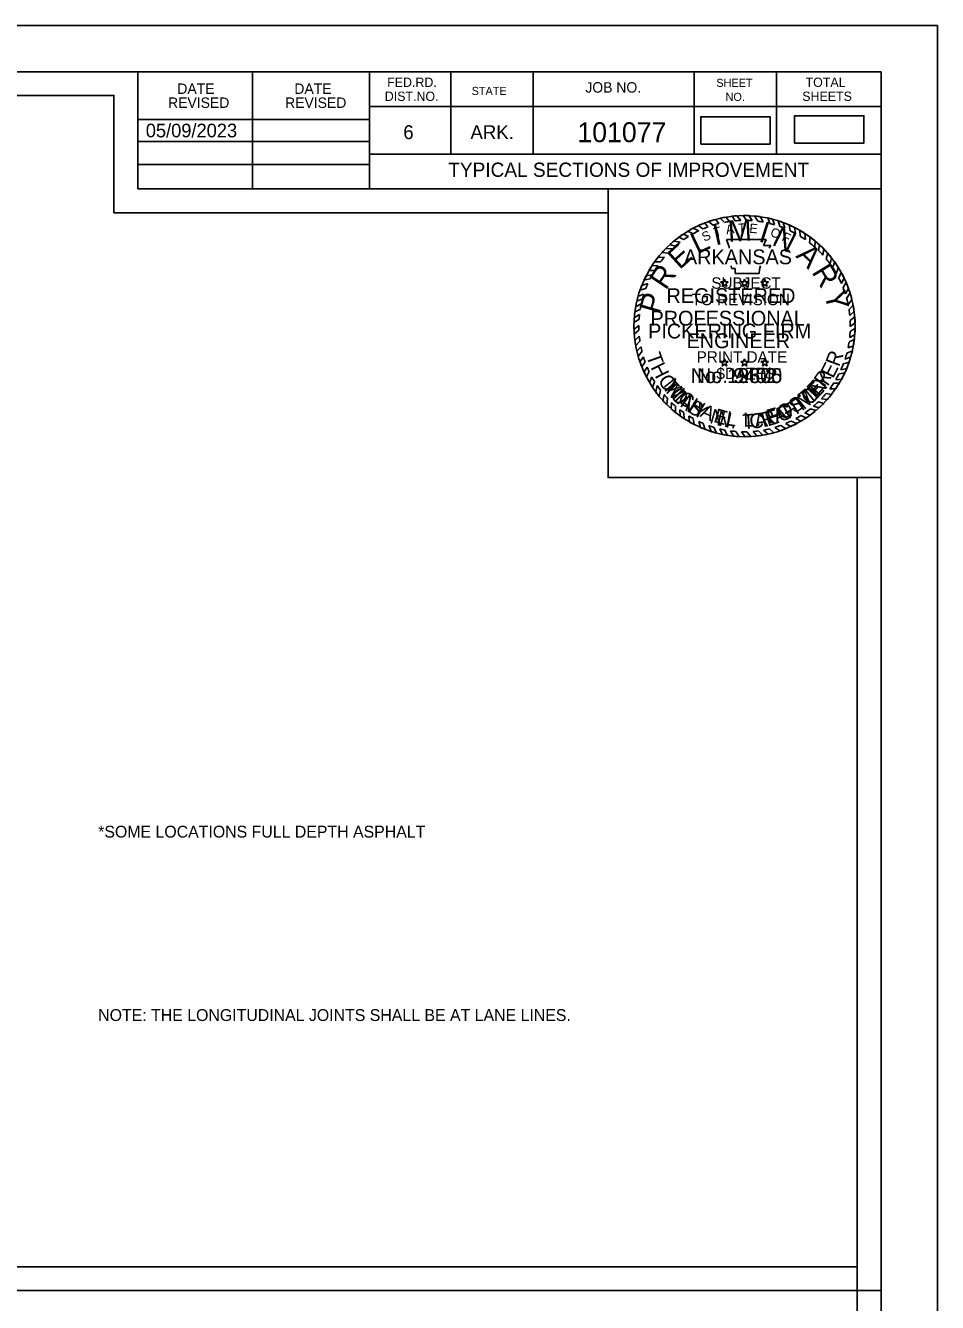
# Model space of a CAD drawing. Extents: x 1368357 to 1371690, y 378199 to 380332.
# Drawn here: x 1370922 to 1371690, y 379256 to 380332 of the extents above; entities that cross this region are included whole.
import ezdxf

# ---------------------------------------------------------------- set-up
doc = ezdxf.new("R2010")
doc.units = 0
for name, color, linetype in [('Default', 7, 'Continuous'), ('R_Border', 7, 'Continuous'), ('R_Border Notes', 7, 'Continuous'), ('R_Border Plan-Plan', 7, 'Continuous'), ('R_No Plot', 7, 'Continuous'), ('R_Revision Date Text', 7, 'Continuous'), ('STAMP_PE_CRAFTON', 7, 'Continuous'), ('STAMP_PE_FOSTER', 7, 'Continuous'), ('STAMP_PE_SEAL-INFO', 7, 'Continuous'), ('STAMP_PE_TAEGTMEYER', 7, 'Continuous'), ('STAMP_PE_TXT', 7, 'Continuous'), ('STAMP_PRELIMINARY', 7, 'Continuous'), ('Text', 7, 'Continuous')]:
    doc.layers.add(name, color=color, linetype=linetype)

msp = doc.modelspace()

# ---------------------------------------------------------------- linework, layer by layer
at = {"layer": 'Default'}
for points in [[(1371490.9, 380232.5), (1371549.3, 380232.5), (1371549.3, 380255.6), (1371490.9, 380255.6)], [(1371570, 380233.3), (1371628.3, 380233.3), (1371628.3, 380256.4), (1371570, 380256.4)]]:
    msp.add_lwpolyline(points, close=True, dxfattribs=at)
at = {"layer": 'R_Border'}
for p, q in [((1368481, 380293.5), (1371642.8, 380293.5)), ((1371016.4, 380194.7), (1371016.4, 380293.5)), ((1371113.2, 380194.7), (1371113.2, 380293.5)), ((1371211.8, 380293.5), (1371211.8, 380194.7)), ((1371280.2, 380293.5), (1371280.2, 380224.1)), ((1371349.6, 380293.5), (1371349.6, 380224.1)), ((1371485.4, 380293.5), (1371485.4, 380224.1)), ((1371554.8, 380293.5), (1371554.8, 380224.1)), ((1371642.8, 378238.9), (1371642.8, 380293.5)), ((1371642.8, 380264.1), (1371211.8, 380264.1)), ((1371642.8, 380264.3), (1371642.8, 380264.3)), ((1371016.4, 380253.3), (1371211.8, 380253.3)), ((1371016.4, 380234.7), (1371211.8, 380234.7)), ((1371642.8, 380224.1), (1371211.8, 380224.1)), ((1371241.4, 380224.1), (1371642.8, 380224.1)), ((1371016.4, 380215.3), (1371211.8, 380215.3)), ((1371642.8, 380194.7), (1371016.4, 380194.7))]:
    msp.add_line(p, q, dxfattribs=at)
at = {"layer": 'R_Border Plan-Plan'}
msp.add_line((1368481, 379266.2), (1371642.8, 379266.2), dxfattribs=at)
at = {"layer": 'R_No Plot'}
for points in [[(1368356.9, 380332.4), (1371690.3, 380332.4), (1371690.3, 378199), (1368356.9, 378199)], [(1371622.8, 379286.2), (1368501, 379286.2), (1368501, 380273.5), (1370996.4, 380273.5), (1370996.4, 380174.7), (1371171.8, 380174.7), (1371412.8, 380174.7), (1371412.8, 379951.4), (1371622.8, 379951.4)], [(1368501, 380273.5), (1370996.4, 380273.5), (1370996.4, 380174.7), (1371171.8, 380174.7), (1371412.8, 380174.7), (1371412.8, 379951.4), (1371622.8, 379951.4), (1371622.8, 378258.9), (1368501, 378258.9)], [(1371412.8, 380194.7), (1371642.8, 380194.7), (1371642.8, 379951.4), (1371412.8, 379951.4)]]:
    msp.add_lwpolyline(points, close=True, dxfattribs=at)
at = {"layer": 'STAMP_PE_SEAL-INFO'}
for p, q in [((1371488.8, 380163.8), (1371492.7, 380161.1)), ((1371493.9, 380166), (1371496.9, 380162.7)), ((1371497.4, 380167.2), (1371501.2, 380164.2)), ((1371503.3, 380169.1), (1371506.2, 380165.6)), ((1371507.2, 380170), (1371510.7, 380166.6)), ((1371512, 380171), (1371515, 380167.3)), ((1371517.2, 380171.7), (1371520, 380167.9)), ((1371524.5, 380168.2), (1371521.4, 380172.1)), ((1371529.5, 380168.2), (1371526.7, 380172.3)), ((1371534.1, 380168), (1371531.5, 380172.3)), ((1371539.1, 380167.5), (1371536.2, 380171.9)), ((1371543.4, 380166.9), (1371540.8, 380171.4)), ((1371549, 380165.7), (1371547.3, 380170.3)), ((1371553, 380164.6), (1371551.4, 380169.3)), ((1371557.5, 380163.1), (1371556.1, 380167.9)), ((1371561.7, 380161.5), (1371560.3, 380166.5)), ((1371566.3, 380159.5), (1371565.3, 380164.4)), ((1371472, 380154.1), (1371476.5, 380152)), ((1371476.2, 380156.7), (1371480.6, 380154.7)), ((1371480.1, 380159.2), (1371484.4, 380156.9)), ((1371484.5, 380161.7), (1371489.2, 380159.4)), ((1371512.5, 380152), (1371546, 380152)), ((1371513.7, 380148.9), (1371512.5, 380152)), ((1371546, 380152), (1371543.7, 380147.1)), ((1371570.8, 380157.2), (1371569.9, 380162.3)), ((1371574.7, 380154.9), (1371574.3, 380159.9)), ((1371579, 380152.1), (1371578.7, 380157.2)), ((1371582.6, 380149.4), (1371583, 380154.3)), ((1371458.2, 380141.1), (1371463.4, 380140.7)), ((1371461.4, 380144.6), (1371466.9, 380144.2)), ((1371464.8, 380147.8), (1371469.4, 380146.4)), ((1371468.2, 380150.8), (1371473.5, 380149.8)), ((1371514.8, 380146), (1371513.7, 380148.9)), ((1371514.9, 380144.8), (1371514.8, 380146)), ((1371543.7, 380147.1), (1371550, 380147.1)), ((1371550, 380147.1), (1371548.6, 380144.8)), ((1371587.1, 380145.7), (1371587.3, 380150.9)), ((1371590.2, 380142.7), (1371590.9, 380147.7)), ((1371593.8, 380139), (1371594.5, 380144.3)), ((1371452, 380133.3), (1371457, 380133.3)), ((1371454.7, 380137), (1371460.2, 380137.2)), ((1371596.5, 380135.8), (1371597.9, 380140.5)), ((1371599.8, 380131.7), (1371601.1, 380136.7)), ((1371602, 380128.5), (1371603.8, 380133.1)), ((1371444.8, 380121.6), (1371449.8, 380122.3)), ((1371447.1, 380125.9), (1371452, 380126.1)), ((1371449.6, 380129.9), (1371454.8, 380130.2)), ((1371516.8, 380127.7), (1371516.5, 380129.9)), ((1371519.9, 380127.7), (1371516.8, 380127.7)), ((1371519.9, 380123.4), (1371519.9, 380127.7)), ((1371540.2, 380123.4), (1371519.9, 380123.4)), ((1371540.4, 380126.8), (1371540.2, 380123.4)), ((1371541.1, 380129.9), (1371540.4, 380126.8)), ((1371605.1, 380123.5), (1371606.9, 380128.5)), ((1371607.1, 380119.9), (1371609.3, 380124.3)), ((1371609.4, 380115), (1371611.6, 380119.9)), ((1371439.6, 380109.3), (1371444.5, 380110.7)), ((1371441.1, 380113.4), (1371446.2, 380114.9)), ((1371443, 380117.7), (1371448, 380118.8)), ((1371610.8, 380111.7), (1371613.4, 380116)), ((1371612.7, 380106.2), (1371615.4, 380110.9)), ((1371437, 380100.2), (1371441.7, 380102.2)), ((1371438, 380104.3), (1371442.8, 380106)), ((1371613.8, 380102.5), (1371616.7, 380107.1)), ((1371615.1, 380096.9), (1371618.3, 380101.4)), ((1371439.2, 380088.8), (1371434.8, 380086)), ((1371439.8, 380093.2), (1371435.3, 380091)), ((1371440.6, 380097.8), (1371436, 380095.3)), ((1371615.8, 380093.1), (1371619.4, 380096.7)), ((1371616.5, 380088), (1371620.2, 380091.4)), ((1371438.8, 380084.6), (1371434.6, 380082)), ((1371438.7, 380079.7), (1371434.6, 380076.3)), ((1371616.8, 380083.9), (1371620.7, 380086.8)), ((1371616.8, 380074.6), (1371621, 380077.4)), ((1371616.9, 380078.7), (1371621, 380081.9)), ((1371438.7, 380075.6), (1371434.8, 380072.3)), ((1371439.1, 380070.6), (1371435.4, 380067.1)), ((1371439.6, 380066.3), (1371436, 380062.6)), ((1371615.9, 380065.7), (1371620.4, 380067.9)), ((1371616.4, 380069.6), (1371620.8, 380072.1)), ((1371440.4, 380061.7), (1371437, 380058.1)), ((1371441.3, 380057.6), (1371438.2, 380053.4)), ((1371613.9, 380056.2), (1371618.7, 380058.2)), ((1371615, 380060.7), (1371619.6, 380062.6)), ((1371442.5, 380053.1), (1371439.6, 380048.9)), ((1371444, 380048.9), (1371441.1, 380044.7)), ((1371445.6, 380044.6), (1371443, 380040.4)), ((1371611.1, 380047.4), (1371615.9, 380048.7)), ((1371612.5, 380051.2), (1371617.4, 380053.2)), ((1371447.3, 380040.8), (1371445.1, 380036.2)), ((1371449.7, 380036.2), (1371447.8, 380031.3)), ((1371604.6, 380033.9), (1371609.7, 380034.5)), ((1371607.4, 380038.9), (1371612.2, 380039.6)), ((1371609, 380042.3), (1371613.9, 380043.3)), ((1371452, 380032.1), (1371450.2, 380027.4)), ((1371454.1, 380029), (1371453, 380023.5)), ((1371456.9, 380025.1), (1371455.9, 380019.8)), ((1371599.5, 380026.2), (1371604.6, 380026.2)), ((1371602.9, 380031.1), (1371607.7, 380031.1)), ((1371459.9, 380021.3), (1371459, 380016.1)), ((1371462.9, 380018), (1371462.3, 380012.7)), ((1371466.2, 380014.7), (1371465.9, 380009.4)), ((1371590.1, 380015.3), (1371594.5, 380013.9)), ((1371592.6, 380017.9), (1371597.4, 380017.1)), ((1371596.5, 380022.3), (1371601.1, 380021.5)), ((1371469.6, 380011.6), (1371469.6, 380006.3)), ((1371473.2, 380008.6), (1371473.4, 380003.4)), ((1371476.6, 380006.1), (1371477, 380001)), ((1371480.9, 380003.3), (1371481.5, 379998.2)), ((1371484.4, 380001.3), (1371485.3, 379996.1)), ((1371571.1, 380001.2), (1371575.3, 379998.9)), ((1371575.3, 380003.7), (1371579.8, 380001.7)), ((1371578.7, 380005.9), (1371583.1, 380004)), ((1371583.3, 380009.4), (1371588, 380007.9)), ((1371586, 380011.6), (1371590.7, 380010.3)), ((1371489.2, 379998.8), (1371490.7, 379993.6)), ((1371492.9, 379997.1), (1371494.6, 379992)), ((1371497.8, 379995.2), (1371499.9, 379990.1)), ((1371501.9, 379993.8), (1371504.2, 379988.9)), ((1371507, 379992.4), (1371509.1, 379987.8)), ((1371511, 379991.6), (1371513.4, 379987)), ((1371516, 379990.8), (1371518.4, 379986.4)), ((1371539.4, 379990.7), (1371543.1, 379987.1)), ((1371543.8, 379991.4), (1371547.7, 379988)), ((1371548.7, 379992.5), (1371552.5, 379989.2)), ((1371553.3, 379993.7), (1371557.5, 379990.7)), ((1371558.3, 379995.3), (1371562.7, 379992.6)), ((1371562.4, 379997), (1371566.7, 379994.4)), ((1371567, 379999.1), (1371571.9, 379997)), ((1371520.3, 379990.3), (1371523.1, 379986)), ((1371525.2, 379990), (1371528.2, 379985.9)), ((1371529.8, 379990), (1371533.2, 379986)), ((1371535, 379990.3), (1371538.2, 379986.5))]:
    msp.add_line(p, q, dxfattribs=at)
for radius, start, end in [(93.2, 111.3124, 114.7026), (89.1, 110.3086, 113.1659), (93.2, 105.2339, 109.0352), (89.1, 104.0352, 107.3615), (93.2, 99.7525, 102.7765), (89.1, 98.258, 101.0329), (93.2, 93.9381, 96.5517), (89.1, 92.1102, 95.0367), (93.2, 87.7298, 90.6707), (89.1, 85.9628, 88.9097), (93.2, 81.9732, 84.8236), (89.1, 79.9264, 82.696), (93.2, 75.3125, 77.9426), (89.1, 73.5575, 76.2314), (93.2, 69.6061, 72.3058), (89.1, 67.6248, 70.504), (93.2, 63.1329, 66.2704), (93.2, 123.6199, 126.5906), (89.1, 121.9746, 125.11), (93.2, 117.6544, 120.8099), (89.1, 115.6869, 119.1583), (89.1, 61.1558, 64.3784), (93.2, 56.9003, 60.0942), (89.1, 54.9238, 58.2702), (93.2, 50.3492, 53.7159), (93.2, 135.4021, 138.3031), (89.1, 133.1331, 136.2562), (93.2, 129.7326, 132.5376), (89.1, 127.5297, 130.9683), (89.1, 48.3016, 52.0395), (89.1, 42.2212, 45.5512), (93.2, 44.3405, 47.3929), (93.2, 141.6056, 144.4486), (89.1, 139.301, 142.5873), (89.1, 36.135, 39.5311), (93.2, 38.1247, 41.2316), (93.2, 31.9614, 35.4294), (93.2, 152.864, 155.5189), (93.2, 147.0072, 149.899), (89.1, 151.0315, 153.573), (89.1, 145.0197, 148.2104), (89.1, 29.9032, 33.6645), (89.1, 23.7732, 27.2211), (93.2, 25.9391, 29.0125), (93.2, 158.4077, 161.0701), (89.1, 156.3402, 159.2319), (89.1, 17.6802, 21.4251), (93.2, 19.9538, 23.3141), (93.2, 164.3068, 166.894), (89.1, 162.4331, 165.0013), (89.1, 11.5444, 15.2364), (93.2, 13.8421, 17.4447), (93.2, 170.0003, 172.6878), (89.1, 173.73, 176.4734), (89.1, 167.9048, 170.9039), (89.1, 5.7599, 9.0606), (93.2, 7.5852, 10.8621), (93.2, 175.7409, 178.2066), (89.1, 179.6454, 182.2633), (89.1, 359.7329, 3.0639), (93.2, 1.7215, 4.7268), (93.2, 355.7156, 358.9569), (93.2, 181.7251, 184.1626), (93.2, 187.4204, 190.1927), (89.1, 185.4539, 188.234), (89.1, 353.8632, 357.1274), (93.2, 349.8305, 353.0885), (93.2, 193.0369, 195.9973), (89.1, 191.2274, 193.9858), (89.1, 341.777, 345.0925), (89.1, 348.0778, 351.3435), (93.2, 343.8925, 347.035), (93.2, 198.8967, 201.6281), (89.1, 196.9675, 199.8353), (89.1, 202.7761, 205.4791), (89.1, 335.6038, 339.1858), (93.2, 337.3837, 340.9933), (93.2, 204.5479, 207.4328), (89.1, 208.7883, 211.7934), (89.1, 329.5549, 333.2076), (93.2, 331.4037, 334.9332), (93.2, 210.8636, 213.6571), (93.2, 216.6115, 219.491), (89.1, 214.1838, 217.2747), (89.1, 323.5851, 327.4407), (93.2, 325.4405, 328.9872), (93.2, 222.48, 225.3801), (89.1, 220.3909, 223.3056), (89.1, 226.2494, 229.2407), (89.1, 310.7744, 314.3161), (93.2, 312.4518, 315.6633), (89.1, 316.6531, 320.3711), (93.2, 318.2846, 321.8043), (93.2, 228.3665, 231.348), (89.1, 232.229, 234.9336), (93.2, 234.295, 236.9452), (89.1, 238.2223, 240.8353), (89.1, 299.0768, 302.1724), (93.2, 300.621, 303.8703), (89.1, 304.823, 308.5143), (93.2, 306.3721, 310.208), (93.2, 240.1977, 242.8613), (89.1, 244.3204, 246.9486), (93.2, 246.576, 249.1558), (89.1, 250.3491, 253.1216), (89.1, 256.505, 259.1192), (89.1, 262.3783, 265.2012), (89.1, 274.6157, 277.4486), (89.1, 280.3459, 283.5814), (89.1, 286.6423, 289.9783), (93.2, 288.5709, 291.9733), (89.1, 292.8745, 296.1185), (93.2, 294.6481, 298.2166), (93.2, 252.5967, 255.3252), (93.2, 258.4433, 261.1398), (93.2, 264.1978, 267.1009), (89.1, 268.3215, 271.277), (93.2, 270.2548, 273.3361), (93.2, 276.4239, 279.4357), (93.2, 282.3199, 285.3702)]:
    msp.add_arc((1371527.8, 380079.1), radius, start, end, dxfattribs=at)
at = {"layer": 'STAMP_PE_TXT'}
for p, q in [((1371509.6, 380114.8), (1371507.6, 380116.3)), ((1371507.6, 380116.3), (1371510.1, 380116.3)), ((1371508.8, 380112.5), (1371509.6, 380114.8)), ((1371510.8, 380113.9), (1371508.8, 380112.5)), ((1371510.1, 380116.3), (1371510.8, 380118.6)), ((1371510.8, 380118.6), (1371511.6, 380116.3)), ((1371512.8, 380112.5), (1371510.8, 380113.9)), ((1371511.6, 380116.3), (1371514, 380116.3)), ((1371514, 380116.3), (1371512, 380114.8)), ((1371512, 380114.8), (1371512.8, 380112.5)), ((1371526.6, 380114.8), (1371524.6, 380116.3)), ((1371524.6, 380116.3), (1371527, 380116.3)), ((1371525.8, 380112.5), (1371526.6, 380114.8)), ((1371527.8, 380113.9), (1371525.8, 380112.5)), ((1371527, 380116.3), (1371527.8, 380118.6)), ((1371527.8, 380118.6), (1371528.6, 380116.3)), ((1371529.8, 380112.5), (1371527.8, 380113.9)), ((1371528.6, 380116.3), (1371531, 380116.3)), ((1371531, 380116.3), (1371529, 380114.8)), ((1371529, 380114.8), (1371529.8, 380112.5)), ((1371543.6, 380114.8), (1371541.6, 380116.3)), ((1371541.6, 380116.3), (1371544, 380116.3)), ((1371542.8, 380112.5), (1371543.6, 380114.8)), ((1371544.8, 380113.9), (1371542.8, 380112.5)), ((1371544, 380116.3), (1371544.8, 380118.6)), ((1371544.8, 380118.6), (1371545.5, 380116.3)), ((1371546.8, 380112.5), (1371544.8, 380113.9)), ((1371545.5, 380116.3), (1371548, 380116.3)), ((1371548, 380116.3), (1371546, 380114.8)), ((1371546, 380114.8), (1371546.8, 380112.5)), ((1371509.6, 380047.7), (1371507.6, 380049.2)), ((1371507.6, 380049.2), (1371510.1, 380049.2)), ((1371508.8, 380045.4), (1371509.6, 380047.7)), ((1371510.8, 380046.9), (1371508.8, 380045.4)), ((1371510.1, 380049.2), (1371510.8, 380051.5)), ((1371510.8, 380051.5), (1371511.6, 380049.2)), ((1371512.8, 380045.4), (1371510.8, 380046.9)), ((1371511.6, 380049.2), (1371514, 380049.2)), ((1371514, 380049.2), (1371512, 380047.7)), ((1371512, 380047.7), (1371512.8, 380045.4)), ((1371526.6, 380047.7), (1371524.6, 380049.2)), ((1371524.6, 380049.2), (1371527, 380049.2)), ((1371525.8, 380045.4), (1371526.6, 380047.7)), ((1371527.8, 380046.9), (1371525.8, 380045.4)), ((1371527, 380049.2), (1371527.8, 380051.5)), ((1371527.8, 380051.5), (1371528.6, 380049.2)), ((1371529.8, 380045.4), (1371527.8, 380046.9)), ((1371528.6, 380049.2), (1371531, 380049.2)), ((1371531, 380049.2), (1371529, 380047.7)), ((1371529, 380047.7), (1371529.8, 380045.4)), ((1371543.6, 380047.7), (1371541.6, 380049.2)), ((1371541.6, 380049.2), (1371544, 380049.2)), ((1371542.8, 380045.4), (1371543.6, 380047.7)), ((1371544.8, 380046.9), (1371542.8, 380045.4)), ((1371544, 380049.2), (1371544.8, 380051.5)), ((1371544.8, 380051.5), (1371545.5, 380049.2)), ((1371546.8, 380045.4), (1371544.8, 380046.9)), ((1371545.5, 380049.2), (1371548, 380049.2)), ((1371548, 380049.2), (1371546, 380047.7)), ((1371546, 380047.7), (1371546.8, 380045.4))]:
    msp.add_line(p, q, dxfattribs=at)
at = {"layer": 'STAMP_PRELIMINARY'}
msp.add_circle((1371527.8, 380079.1), 93.2, dxfattribs=at)

# ---------------------------------------------------------------- texts
at = {"layer": 'R_Border'}
for s, height, p in [('DATE', 8.79, (1371049.8, 380274.8)), ('DATE', 8.79, (1371148.4, 380274.8)), ('FED.RD.', 7.82, (1371226.6, 380280.7)), ('JOB NO.', 8.79, (1371393.6, 380275.9)), ('SHEET', 6.84, (1371504, 380280.7)), ('TOTAL', 7.82, (1371579.2, 380280.7)), ('REVISED', 8.79, (1371042, 380263)), ('REVISED', 8.79, (1371140.6, 380263)), ('DIST.NO.', 7.82, (1371224.6, 380268.9)), ('STATE', 6.84, (1371297.8, 380273.9)), ('NO.', 6.84, (1371511.8, 380268.9)), ('SHEETS', 7.82, (1371576.4, 380268.9)), ('6', 11.7, (1371240.2, 380236.7)), ('ARK.', 11.72, (1371296.8, 380236.7))]:
    msp.add_text(s, height=height, dxfattribs=at).set_placement(p)
at = {"layer": 'R_Border Notes'}
for s, height, p in [('101077', 16.8, (1371386.9, 380234.1)), ('TYPICAL SECTIONS OF IMPROVEMENT', 12, (1371278.1, 380204.9))]:
    msp.add_text(s, height=height, dxfattribs=at).set_placement(p)
at = {"layer": 'R_Revision Date Text'}
msp.add_text('05/09/2023', height=11.5, dxfattribs=at).set_placement((1371023.2, 380238.2))
at = {"layer": 'STAMP_PE_CRAFTON'}
for s, rotation, p in [('T', 310.7442, (1371457.5, 380028.1)), ('N', 49.2411, (1371590.6, 380019.3)), ('O', 317.6422, (1371464.1, 380020)), ('O', 41.8391, (1371582.2, 380011.5)), ('N', 324.4537, (1371472.6, 380012.1)), ('Y', 331.1686, (1371482.9, 380005)), ('F', 28.7821, (1371564.4, 380000.4)), ('T', 34.1136, (1371573.6, 380005.5)), ('N', 347.4752, (1371503.5, 379995.8)), ('C', 6.0117, (1371532.5, 379992.5)), ('R', 14.8189, (1371543.5, 379993.7)), ('A', 20.5125, (1371554.6, 379996.7)), ('.', 356.8926, (1371515.8, 379993))]:
    msp.add_text(s, height=12.5, rotation=rotation, dxfattribs=at).set_placement(p)
msp.add_text('No. 12370', height=12.5, dxfattribs=at).set_placement((1371482.4, 380031.1))
at = {"layer": 'STAMP_PE_FOSTER'}
for s, rotation, p in [('M', 308.339, (1371459, 380029.3)), ('E', 46.9613, (1371587.8, 380019)), ('R', 54.5031, (1371595, 380027.2)), ('I', 314.1842, (1371466.9, 380019.9)), ('C', 319.8733, (1371470.5, 380016.4)), ('T', 39.4194, (1371579.2, 380011.5)), ('H', 327.7235, (1371479.8, 380009.1)), ('A', 335.7276, (1371489.6, 380003.2)), ('O', 23.719, (1371558.6, 379999.9)), ('S', 31.7234, (1371569.7, 380005.2)), ('E', 343.5779, (1371501, 379998.5)), ('L', 350.8115, (1371511.5, 379995.8)), ('L', 1.2666, (1371526.9, 379994.2)), ('F', 15.8691, (1371548.2, 379996.7)), ('.', 6.8035, (1371537.4, 379994.8))]:
    msp.add_text(s, height=12, rotation=rotation, dxfattribs=at).set_placement(p)
msp.add_text('No. 9402', height=12.5, dxfattribs=at).set_placement((1371487.7, 380031.1))
at = {"layer": 'STAMP_PE_TAEGTMEYER'}
for s, rotation, p in [('T', 289.646, (1371444.7, 380054.2)), ('R', 69.57, (1371607.3, 380044.2)), ('H', 296.7339, (1371448.3, 380044.4)), ('E', 63.0984, (1371602.3, 380034.4)), ('O', 303.7708, (1371454.3, 380033.3)), ('Y', 53.9986, (1371595.6, 380025)), ('M', 314.2033, (1371460.8, 380023.8)), ('M', 39.3, (1371577.8, 380008.1)), ('E', 46.8094, (1371588.2, 380016.9)), ('A', 321.0594, (1371470.4, 380014.1)), ('S', 327.8239, (1371478.7, 380007.7)), ('G', 23.3052, (1371557.8, 379997.7)), ('T', 31.466, (1371568.8, 380002.7)), ('N', 344.2727, (1371497.7, 379997.6)), ('T', 3.0061, (1371526.4, 379992.3)), ('A', 8.9826, (1371536.9, 379992.9)), ('E', 17.6836, (1371547.3, 379994.4)), ('.', 350.6464, (1371509.8, 379994.3))]:
    msp.add_text(s, height=12.5, rotation=rotation, dxfattribs=at).set_placement(p)
msp.add_text('No. 19605', height=12.5, dxfattribs=at).set_placement((1371482.4, 380031.1))
at = {"layer": 'STAMP_PE_TXT'}
for s, rotation, p in [('T', 16.311, (1371503, 380153.9)), ('A', 9.0679, (1371512.6, 380156.4)), ('T', 1.8248, (1371522.5, 380157.7)), ('E', 355.2002, (1371531.6, 380157.8)), ('S', 23.5541, (1371493.8, 380150.1)), ('O', 342.2506, (1371548.9, 380155)), ('F', 335.0075, (1371558.5, 380151.6))]:
    msp.add_text(s, height=7.81, rotation=rotation, dxfattribs=at).set_placement(p)
for s, p in [('ARKANSAS', (1371476.7, 380131.2)), ('REGISTERED', (1371462, 380098.5)), ('PROFESSIONAL', (1371448.5, 380079.5)), ('ENGINEER', (1371478.9, 380060.5))]:
    msp.add_text(s, height=12.5, dxfattribs=at).set_placement(p)
at = {"layer": 'STAMP_PRELIMINARY'}
for s, rotation, p in [('I', 12.5248, (1371503.2, 380147)), ('M', 3.1074, (1371514.2, 380150.1)), ('I', 342.3164, (1371538.8, 380150.7)), ('N', 333.9382, (1371549.9, 380148)), ('L', 25.513, (1371487.9, 380139.4)), ('E', 42.3578, (1371473.1, 380126.1)), ('A', 315.6579, (1371570.2, 380137.7)), ('R', 301.3831, (1371583.9, 380124.6)), ('R', 56.2292, (1371461.5, 380108.7)), ('Y', 283.2593, (1371594.8, 380106.7)), ('P', 73.913, (1371456, 380088.5))]:
    msp.add_text(s, height=18, rotation=rotation, dxfattribs=at).set_placement(p)
for s, height, p in [('SUBJECT', 9.6, (1371499.8, 380110.6)), ('TO REVISION', 9.6, (1371483.2, 380096.7)), ('PICKERING FIRM', 12.5, (1371446.5, 380068.7)), ('PRINT DATE', 9.6, (1371487.4, 380048.3)), ('$DATE$', 9.6, (1371504.1, 380034.4))]:
    msp.add_text(s, height=height, dxfattribs=at).set_placement(p)
at = {"layer": 'Text'}
for s, p in [('*SOME LOCATIONS FULL DEPTH ASPHALT', (1370983.1, 379648)), ('NOTE: THE LONGITUDINAL JOINTS SHALL BE AT LANE LINES.', (1370983.1, 379493.4))]:
    msp.add_text(s, height=10, dxfattribs=at).set_placement(p)

doc.saveas('drawing.dxf')
